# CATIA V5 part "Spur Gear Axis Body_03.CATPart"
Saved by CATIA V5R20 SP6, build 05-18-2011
Part number: Spur Gear Axis Body_03
Bounding box of the stored display mesh (mm): x 0 to 10, y -10 to 10, z -10 to 10
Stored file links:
  E:\#01 CATIA Lecture Materials\#06 DMU\#10 Kinematics Joints\#002 Gear Joint(Spur Gear)\Spur Gear Axis Body_03.CATPart
  E:\#01 CATIA Lecture Materials\#06 DMU\#10 Kinematics Joints\#002 Gear Joint(Spur Gear)\Spur Gear Assembly Kinematics.CATProduct
  E:\#01 CATIA Lecture Materials\#06 DMU\#10 Kinematics Joints\#002 Gear Joint(Spur Gear)\Spur Gear Template_(2 Row).CATPart
  E:\#01 CATIA Lecture Materials\#06 DMU\#10 Kinematics Joints\#002 Gear Joint(Spur Gear)\Spur Gear (Z=25).CATPart
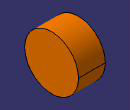
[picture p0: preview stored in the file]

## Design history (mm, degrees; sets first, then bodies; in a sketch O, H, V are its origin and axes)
Set1 "Reference Data"
  Point1 "Center Point": (0, 0, 0)
Body1 (main body)
  Sketch1 on yz-plane, origin (0, 0, 0), H (0, 1, 0), V (0, 0, 1)
    circle A1 centre (0, 0) radius 10
    radius A1 = 10
  Pad1: profile Sketch1, direction (1, 0, 0), length 10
